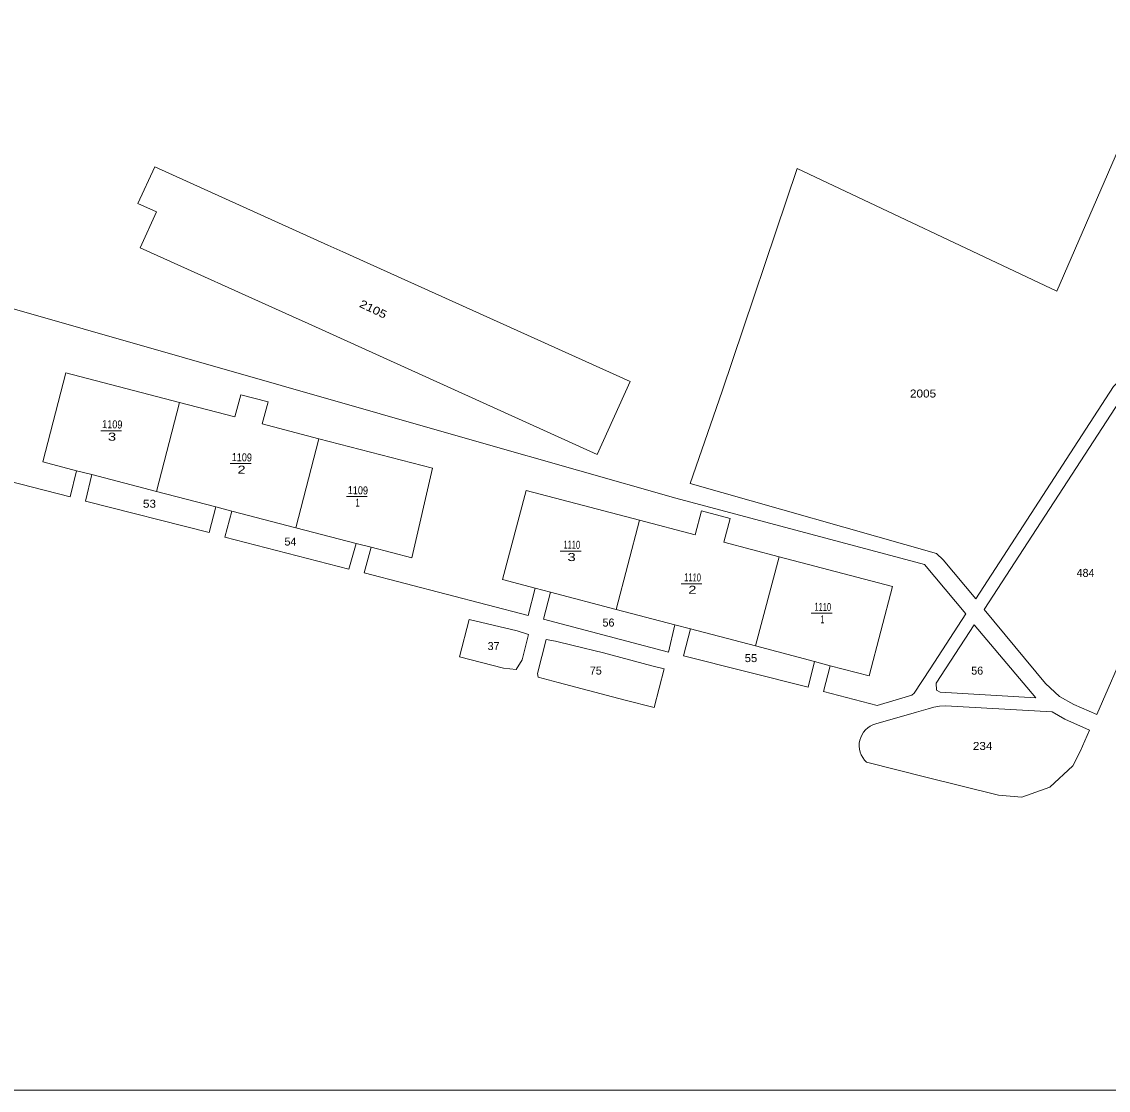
# Model space of a CAD drawing. Extents: x -843400 to -842830, y -1002860 to -1002082.
# Drawn here: x -843097.6 to -842961.8, y -1002860 to -1002726.5 of the extents above; entities that cross this region are included whole.
import ezdxf
from ezdxf.enums import TextEntityAlignment as Align

# ---------------------------------------------------------------- set-up
doc = ezdxf.new("R2010")
doc.units = 0
doc.header["$LTSCALE"] = 0.4
for name, color, linetype, lineweight in [('35', 7, 'Continuous', 13), ('38', 7, 'Continuous', 13), ('43', 7, 'Continuous', 13), ('44', 7, 'Continuous', 13)]:
    doc.layers.add(name, color=color, linetype=linetype, lineweight=lineweight)

msp = doc.modelspace()

# ---------------------------------------------------------------- linework, layer by layer
at = {"layer": '35'}
for p, q in [((-843087.723, -1002777.573), (-843085.127, -1002777.573)), ((-843071.54, -1002781.694), (-843068.944, -1002781.694)), ((-843057.036, -1002785.815), (-843054.44, -1002785.815)), ((-843030.3, -1002792.613), (-843027.704, -1002792.613)), ((-843015.206, -1002796.701), (-843012.61, -1002796.701)), ((-842998.94, -1002800.389), (-842996.344, -1002800.389))]:
    msp.add_line(p, q, dxfattribs=at)
at = {"layer": '38'}
for p, q in [((-843077.88, -1002774.04), (-843080.77, -1002785.18)), ((-843060.46, -1002778.58), (-843063.35, -1002789.71)), ((-843088.86, -1002783.07), (-843090.74, -1002782.58)), ((-843071.35, -1002787.63), (-843073.34, -1002787.11)), ((-843020.41, -1002788.77), (-843023.33, -1002799.9)), ((-843053.94, -1002792.15), (-843055.81, -1002791.67)), ((-843005.9, -1002804.48), (-843002.97, -1002793.34)), ((-843031.53, -1002797.74), (-843033.44, -1002797.24)), ((-843014.04, -1002802.34), (-843015.99, -1002801.83)), ((-842998.53, -1002806.42), (-842996.56, -1002806.94))]:
    msp.add_line(p, q, dxfattribs=at)
msp.add_lwpolyline([(-843021.56, -1002771.43), (-843025.68, -1002780.53), (-843061.79, -1002764.2), (-843063.75, -1002763.32), (-843082.79, -1002754.71), (-843080.76, -1002750.23), (-843083.08, -1002749.18), (-843080.99, -1002744.59), (-843059.35, -1002754.38), (-843057.46, -1002755.23)], close=True, dxfattribs=at)
at = {"layer": '43'}
for points in [[(-842940.49, -1002696.12), (-842968.25, -1002760.14), (-843000.72, -1002744.8), (-843010.07, -1002772.62), (-843014.071, -1002784.19), (-842983.31, -1002792.93), (-842982.45, -1002793.71), (-842978.37, -1002798.58), (-842961.17, -1002772.04), (-842959.01, -1002769.99), (-842956.6, -1002769.16), (-842957.64, -1002757.28), (-842957.86, -1002749.53), (-842956.98, -1002741.66), (-842953.8, -1002732.13), (-842944.4, -1002710.39)], [(-843127.075, -1002754.205), (-843040.429, -1002779.029), (-843015.852, -1002786.007), (-842984.787, -1002794.307), (-842979.62, -1002800.48), (-842984.08, -1002807.32), (-842986.08, -1002810.38), (-842986.38, -1002810.62), (-842990.7, -1002811.9), (-842997.43, -1002810.15), (-842996.56, -1002806.94), (-842991.71, -1002808.21), (-842988.78, -1002797.06), (-843002.97, -1002793.34), (-843009.87, -1002791.52), (-843009.09, -1002788.55), (-843012.67, -1002787.6), (-843013.45, -1002790.58), (-843020.41, -1002788.77), (-843034.58, -1002785.04), (-843037.51, -1002796.17), (-843033.44, -1002797.24), (-843034.31, -1002800.65), (-843054.81, -1002795.35), (-843053.94, -1002792.15), (-843048.84, -1002793.48), (-843046.26, -1002782.27), (-843060.46, -1002778.58), (-843067.54, -1002776.72), (-843066.82, -1002773.97), (-843070.24, -1002773.08), (-843070.96, -1002775.84), (-843077.88, -1002774.04), (-843092.08, -1002770.34), (-843094.98, -1002781.48), (-843090.74, -1002782.58), (-843091.57, -1002785.84), (-843116.6, -1002779.43)], [(-842990.87, -1002814.2), (-842985.79, -1002812.74), (-842984.35, -1002812.33), (-842983.61, -1002812.12), (-842982.92, -1002811.99), (-842982.16, -1002811.97), (-842968.84, -1002812.71), (-842967.27, -1002813.62), (-842964.16, -1002815), (-842965.33, -1002817.67), (-842966.24, -1002819.45), (-842969.14, -1002822.12), (-842972.61, -1002823.36), (-842975.554, -1002823.116), (-842984.636, -1002820.877), (-842992.026, -1002819.01)]]:
    msp.add_lwpolyline(points, dxfattribs=at)
for points in [[(-842963.26, -1002813.05), (-842959.28, -1002803.94), (-842957.93, -1002800.07), (-842957.1, -1002797.33), (-842955.81, -1002788.38), (-842955.61, -1002780.41), (-842956.41, -1002771.1), (-842958.35, -1002771.68), (-842959.84, -1002773), (-842977.33, -1002799.92), (-842969.68, -1002809.15), (-842967.9, -1002810.77), (-842966.14, -1002811.8)], [(-843073.34, -1002787.11), (-843074.16, -1002790.3), (-843089.65, -1002786.37), (-843088.86, -1002783.07), (-843080.77, -1002785.18)], [(-843063.35, -1002789.71), (-843055.81, -1002791.67), (-843056.73, -1002794.87), (-843072.22, -1002790.88), (-843071.35, -1002787.63)], [(-843015.99, -1002801.83), (-843016.76, -1002805.24), (-843032.39, -1002801.12), (-843031.53, -1002797.74), (-843023.33, -1002799.9)], [(-843041.701, -1002801.182), (-843035.71, -1002802.59), (-843034.27, -1002803.04), (-843035.05, -1002806.21), (-843035.83, -1002807.4), (-843037.413, -1002807.249), (-843042.907, -1002805.819)], [(-842978.58, -1002801.82), (-842983.32, -1002809.12), (-842983.29, -1002809.98), (-842982.82, -1002810.25), (-842970.88, -1002810.94)], [(-843005.9, -1002804.48), (-842998.53, -1002806.42), (-842999.34, -1002809.64), (-843014.9, -1002805.72), (-843014.04, -1002802.34)], [(-843018.575, -1002812.177), (-843022.188, -1002811.231), (-843030.553, -1002809.033), (-843033.083, -1002808.368), (-843033.17, -1002807.9), (-843032.06, -1002803.67), (-843030.89, -1002803.87), (-843028.68, -1002804.43), (-843024.91, -1002805.35), (-843018.85, -1002806.95), (-843017.312, -1002807.349)]]:
    msp.add_lwpolyline(points, close=True, dxfattribs=at)
msp.add_arc((-842990.1344, -1002816.9206), 2.8183, 105.13049, 227.84264, dxfattribs=at)
at = {"layer": '44'}
msp.add_lwpolyline([(-842830.097, -1002859.997), (-842830.097, -1002081.989), (-843400.094, -1002081.989), (-843400.094, -1002859.997)], close=True, dxfattribs=at)

# ---------------------------------------------------------------- texts
at = {"layer": '35'}
for s, height, rotation, width, p in [('2105', 0.999, 334.446, 1.2, (-843053.891, -1002762.8381)), ('1109', 1, 358.734, 0.85, (-843086.294, -1002777.2766)), ('3', 1, 358.734, 1.4, (-843086.3285, -1002778.8255)), ('1109', 1, 358.734, 0.85, (-843070.1115, -1002781.3975)), ('2', 1, 358.734, 1.35, (-843070.145, -1002782.9463)), ('1109', 1, 358.734, 0.85, (-843055.6075, -1002785.5175)), ('1', 1, 358.734, 0.7, (-843055.6415, -1002787.0678)), ('1110', 1, 358.734, 0.7, (-843028.8705, -1002792.316)), ('3', 1, 358.734, 1.4, (-843028.9055, -1002793.8655)), ('1110', 1, 358.734, 0.7, (-843013.777, -1002796.404)), ('2', 1, 358.734, 1.35, (-843013.811, -1002797.9533)), ('1110', 1, 358.734, 0.7, (-842997.5095, -1002800.092)), ('1', 1, 358.734, 0.7, (-842997.5455, -1002801.6408))]:
    msp.add_text(s, height=height, rotation=rotation, dxfattribs=dict(at, width=width)).set_placement(p, align=Align.CENTER)
at = {"layer": '43'}
for s, width, p in [('2005', 1.1, (-842986.609, -1002773.432)), ('53', 1.1, (-843082.458, -1002787.202)), ('55', 1.05, (-843007.255, -1002806.491)), ('234', 1.1, (-842978.75, -1002817.471))]:
    msp.add_text(s, height=1, dxfattribs=dict(at, width=width)).set_placement(p)
for s, p in [('54', (-843064.77, -1002791.93)), ('484', (-842965.785, -1002795.845)), ('56', (-843025.022, -1002802.052)), ('37', (-843039.382, -1002804.987)), ('75', (-843026.609, -1002808.052)), ('56', (-842978.949, -1002808.059))]:
    msp.add_text(s, height=1, dxfattribs=at).set_placement(p)

doc.saveas('drawing.dxf')
